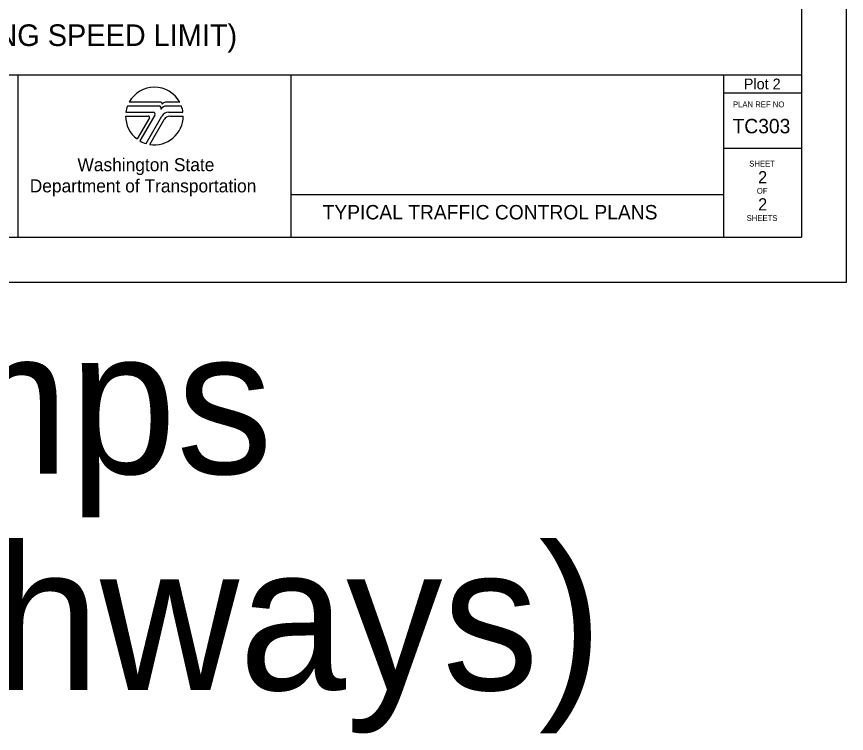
# Model space of a CAD drawing. Extents: x 99999.1 to 100055.7, y 99995 to 100013.2.
# Drawn here: x 100030.3 to 100036.06, y 99996.56 to 100001.53 of the extents above; entities that cross this region are included whole.
import ezdxf

# ---------------------------------------------------------------- set-up
doc = ezdxf.new("R2010")
doc.units = 0
for name, color, linetype in [('SH_DE_DetailHeading1Text', 7, 'Continuous'), ('SH_GI_PlotLimits', 7, 'Continuous'), ('SH_GI_SheetBorder', 7, 'Continuous'), ('SH_GI_SheetLocationText', 7, 'Continuous'), ('SH_GI_SheetTextInCells', 7, 'Continuous'), ('SH_GI_TitleBlockText', 7, 'Continuous'), ('SH_GI_WSDOTLogo', 7, 'Continuous')]:
    doc.layers.add(name, color=color, linetype=linetype)

msp = doc.modelspace()

# ---------------------------------------------------------------- linework, layer by layer
at = {"layer": 'SH_GI_PlotLimits'}
msp.add_lwpolyline([(100019.0625, 99999.6875), (100036.0625, 99999.6875), (100036.0625, 100010.6875), (100019.0625, 100010.6875)], close=True, dxfattribs=at)
at = {"layer": 'SH_GI_SheetBorder'}
for p, q in [((100035.75, 100010.375), (100035.75, 100000)), ((100020, 100001.1259), (100035.75, 100001.1259)), ((100030.3089, 100001.1259), (100030.3089, 100000)), ((100032.2055, 100001.1259), (100032.2055, 100000)), ((100035.2079, 100001.1259), (100035.2079, 100000)), ((100035.2079, 100001.0008), (100035.75, 100001.0008)), ((100035.2079, 100000.6176), (100035.75, 100000.6176)), ((100032.2055, 100000.2955), (100035.2079, 100000.2955)), ((100020, 100000), (100035.75, 100000))]:
    msp.add_line(p, q, dxfattribs=at)
at = {"layer": 'SH_GI_WSDOTLogo'}
for p, q in [((100031.2894, 100000.9094), (100031.0697, 100000.9094)), ((100031.303, 100000.9354), (100031.0815, 100000.9354)), ((100031.433, 100000.9354), (100031.3351, 100000.9354)), ((100031.343, 100000.9094), (100031.3429, 100000.9094)), ((100031.4448, 100000.9094), (100031.343, 100000.9094)), ((100031.0572, 100000.84), (100031.2148, 100000.84)), ((100031.059, 100000.8661), (100031.2496, 100000.8661)), ((100031.261, 100000.8464), (100031.1567, 100000.6672)), ((100031.1989, 100000.6487), (100031.3089, 100000.839)), ((100031.3558, 100000.8661), (100031.4555, 100000.8661)), ((100031.3655, 100000.8394), (100031.4572, 100000.8394)), ((100031.222, 100000.8277), (100031.1364, 100000.6807)), ((100031.2244, 100000.6428), (100031.3242, 100000.8156))]:
    msp.add_line(p, q, dxfattribs=at)
for centre, radius, start, end in [((100031.2572, 100000.84), 0.2, 28.47865, 151.53204), ((100031.2572, 100000.84), 0.2, 159.69598, 172.50569), ((100031.2894, 100000.8946), 0.0148, 327.8418, 89.99855), ((100031.3429, 100000.861), 0.0484, 89.99529, 147.82376), ((100031.303, 100000.9263), 0.00903, 329.87418, 90.00328), ((100031.3352, 100000.9066), 0.0287, 90.00721, 148.16763), ((100031.2572, 100000.84), 0.2, 7.49431, 20.29406), ((100031.2572, 100000.84), 0.2, 179.99864, 232.84327), ((100031.2149, 100000.8318), 0.0082, 329.74356, 90), ((100031.2572, 100000.84), 0.2, 260.54554, 359.80857), ((100031.2497, 100000.853), 0.0131, 329.76834, 90), ((100031.3558, 100000.8119), 0.0542, 90, 149.99738), ((100031.3654, 100000.7918), 0.0476, 90, 150.05432), ((100031.2572, 100000.84), 0.2, 239.79292, 253.0448)]:
    msp.add_arc(centre, radius, start, end, dxfattribs=at)

# ---------------------------------------------------------------- texts
at = {"layer": 'SH_DE_DetailHeading1Text'}
msp.add_text('FREEWAY (2+ LANES): RIGHT SHOULDER CLOSURE (MAINTAIN EXISTING SPEED LIMIT)', height=0.15, rotation=360, dxfattribs=at).set_placement((100023.3333, 100001.3259))
at = {"layer": 'SH_GI_SheetBorder'}
msp.add_text('PLAN REF NO', height=0.040032, dxfattribs=at).set_placement((100035.2747, 100000.9008))
at = {"layer": 'SH_GI_SheetLocationText'}
for s, height, p in [('Plot 2', 0.075, (100035.3497, 100001.025)), ('Right Ramps', 1, (100024.3498, 99998.3571)), ('(45+ mph Highways)', 1, (100022.071, 99996.8571))]:
    msp.add_text(s, height=height, dxfattribs=at).set_placement(p)
at = {"layer": 'SH_GI_SheetTextInCells'}
for s, height, p in [('Washington State', 0.090072, (100030.7229, 100000.4571)), ('SHEET', 0.04003, (100035.3877, 100000.4896)), ('Department of Transportation', 0.090072, (100030.3916, 100000.3101)), ('OF', 0.04003, (100035.4406, 100000.3008)), ('SHEETS', 0.04003, (100035.3698, 100000.112))]:
    msp.add_text(s, height=height, dxfattribs=at).set_placement(p)
at = {"layer": 'SH_GI_TitleBlockText'}
for s, height, p in [('TC303', 0.1, (100035.2718, 100000.72)), ('2', 0.085, (100035.4493, 100000.3723)), ('2', 0.085, (100035.4493, 100000.1843)), ('TYPICAL TRAFFIC CONTROL PLANS', 0.1, (100032.4251, 100000.1224))]:
    msp.add_text(s, height=height, dxfattribs=at).set_placement(p)

doc.saveas('drawing.dxf')
